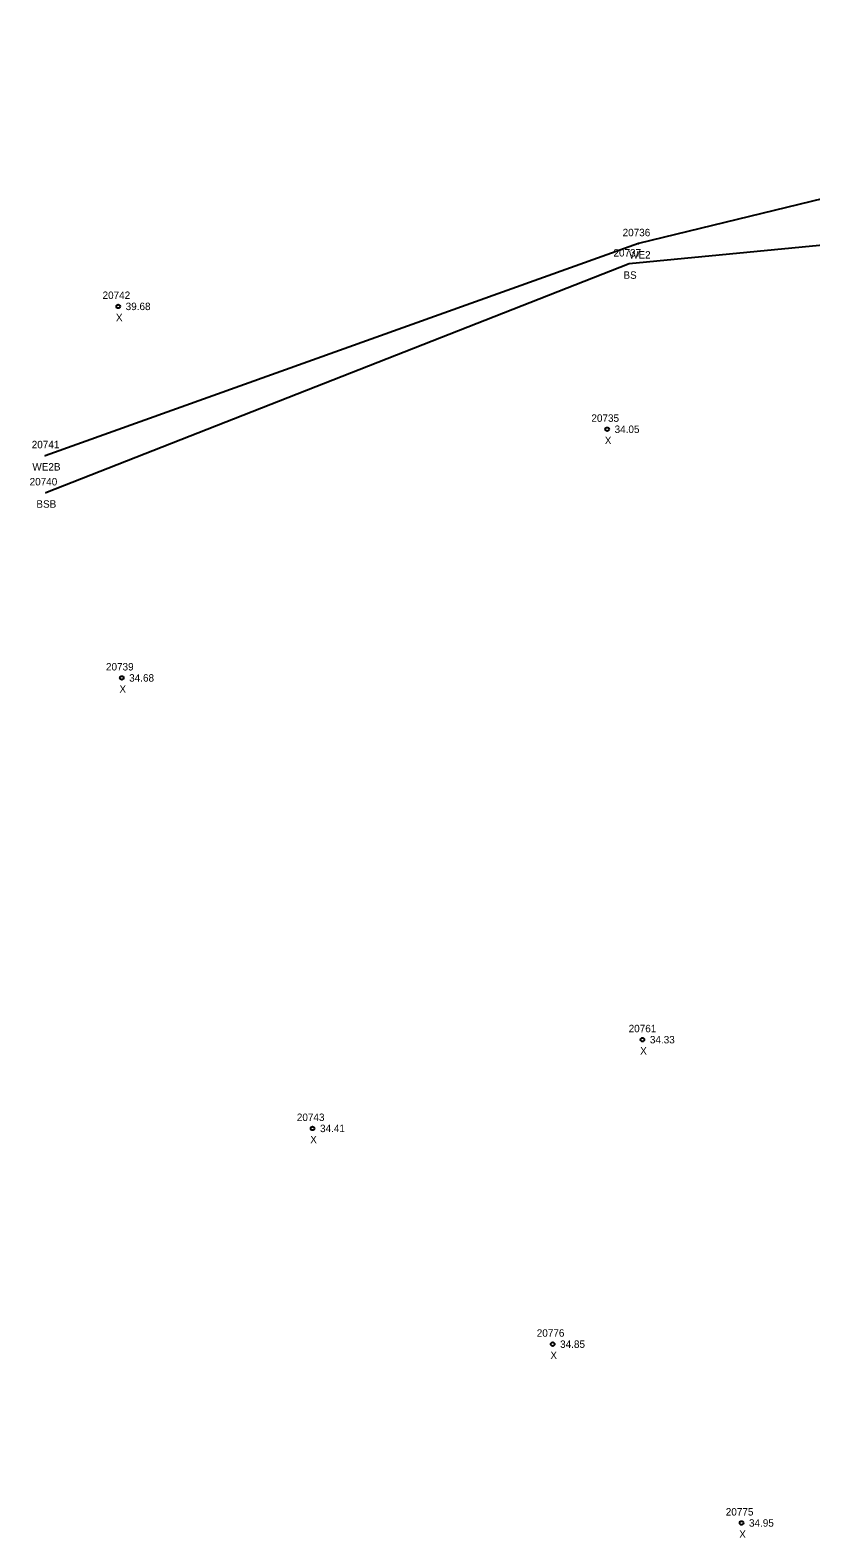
# Model space of a CAD drawing. Extents: x 2445178 to 2446260, y 791158 to 792318.
# Drawn here: x 2445177.5 to 2445282.6, y 791577.9 to 791780.8 of the extents above; entities that cross this region are included whole.
import ezdxf

# ---------------------------------------------------------------- set-up
doc = ezdxf.new("R2010")
doc.units = 0
for name, color, linetype in [('RD_DTM_BkLn2', 7, 'Continuous'), ('RD_EX_H2O', 7, 'Continuous'), ('RD_EX_H2O_txCode', 7, 'Continuous'), ('RD_Sketch8', 7, 'Continuous'), ('RD_SMD_Locator', 7, 'Continuous'), ('RD_SMD_Misc', 7, 'Continuous')]:
    doc.layers.add(name, color=color, linetype=linetype)

msp = doc.modelspace()

# ---------------------------------------------------------------- linework, layer by layer
at = {"layer": 'RD_DTM_BkLn2'}
msp.add_lwpolyline([(2445394.99, 791911.52), (2445386.85, 791818.37), (2445340.06, 791757.26), (2445258.15, 791749.35), (2445179.64, 791718.55)], dxfattribs=at)
at = {"layer": 'RD_EX_H2O'}
msp.add_lwpolyline([(2445390.88, 791910.3), (2445382.88, 791823.37), (2445332.21, 791769.8), (2445259.4, 791752.08), (2445179.59, 791723.55)], dxfattribs=at)
at = {"layer": 'RD_SMD_Locator'}
for centre, radius in [((2445259.4, 791752.08), 0.001), ((2445258.15, 791749.35), 0.001), ((2445189.4, 791743.64), 0.25), ((2445255.18, 791727.11), 0.25), ((2445179.59, 791723.55), 0.001), ((2445179.64, 791718.55), 0.001), ((2445189.87, 791693.65), 0.25), ((2445259.93, 791644.97), 0.25), ((2445215.55, 791633.03), 0.25), ((2445247.85, 791604), 0.25), ((2445273.26, 791579.94), 0.25)]:
    msp.add_circle(centre, radius, dxfattribs=at)

# ---------------------------------------------------------------- texts
at = {"layer": 'RD_EX_H2O_txCode'}
for s, p in [('20736', (2445257.26, 791753.08)), ('WE2', (2445258.13, 791750.08)), ('20741', (2445177.76, 791724.55)), ('WE2B', (2445177.85, 791721.55))]:
    msp.add_text(s, height=1, dxfattribs=at).set_placement(p)
at = {"layer": 'RD_Sketch8'}
for s, p in [('20742', (2445187.29, 791744.64)), ('39.68', (2445190.4, 791743.14)), ('X', (2445189.09, 791741.64)), ('20735', (2445253.06, 791728.11)), ('X', (2445254.86, 791725.11)), ('34.05', (2445256.18, 791726.61)), ('20739', (2445187.75, 791694.65)), ('34.68', (2445190.87, 791693.15)), ('X', (2445189.56, 791691.65)), ('20761', (2445258.07, 791645.97)), ('34.33', (2445260.93, 791644.47)), ('X', (2445259.62, 791642.97)), ('20743', (2445213.43, 791634.03)), ('34.41', (2445216.55, 791632.53)), ('X', (2445215.23, 791631.03)), ('20776', (2445245.71, 791605)), ('34.85', (2445248.85, 791603.5)), ('X', (2445247.54, 791602)), ('20775', (2445271.14, 791580.94)), ('34.95', (2445274.26, 791579.44)), ('X', (2445272.95, 791577.94))]:
    msp.add_text(s, height=1, dxfattribs=at).set_placement(p)
at = {"layer": 'RD_SMD_Misc'}
for s, p in [('20737', (2445256.03, 791750.35)), ('BS', (2445257.37, 791747.35)), ('20740', (2445177.48, 791719.55)), ('BSB', (2445178.39, 791716.55))]:
    msp.add_text(s, height=1, dxfattribs=at).set_placement(p)

doc.saveas('drawing.dxf')
